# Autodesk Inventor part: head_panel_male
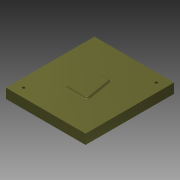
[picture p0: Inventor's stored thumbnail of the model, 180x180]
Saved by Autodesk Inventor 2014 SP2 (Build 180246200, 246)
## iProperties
Created: 2015-02
Part Number: head_panel_male
Material: Generic
Document SubType Name: Modeling
Designer: s41632
Density: 1 g/cm^3
Appearance: Titanium
Author: s41632
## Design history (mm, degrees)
sketch "Sketch9"
  geometry: L1 (0, 0)-(180, 0); L2 (180, 0)-(180, 200); L3 (180, 200)-(0, 200); L4 (0, 200)-(0, 0)
  constraints: 8 end point, 2 parallel, 1 horizontal, 1 perpendicular
  dimensions: "d73" = 200 distance of L3.end L1.start; "d74" = 180 distance between parallel lines of L4 L2
extrude "Extrusion7" new body sketch "Sketch9" distance "d75" = 22; taper "d76" = 0 deg
sketch "Sketch11"
  geometry: L1 (180, 0)-(180, 200) reference; L2 (180, 200)-(0, 200) reference; L3 (0, 200)-(0, 0) reference; L4 (65, 70)-(115, 70); L5 (115, 70)-(105, 130); L6 (105, 130)-(75, 130); L7 (75, 130)-(65, 70); 6 further points
  constraints: 8 end point, 6 midpoint, 2 horizontal alignment, 2 vertical alignment, 1 parallel, 1 perpendicular
  dimensions: "d80" = 30 distance of L5.end L6.end; "d81" = 50 distance of L4.start L4.end; "d82" = 60 distance between parallel lines of L6 L4
extrude "Extrusion8" join sketch "Sketch11" distance "d83" = 3; taper "d84" = 0 deg
fillet "Fillet3" dims "d85" = 5
fillet "Fillet4" dims "d86" = 3
fillet "Fillet5" dims "d87" = 3
sketch "Sketch12"
  geometry: L1 (0, 0)-(180, 0) reference; L2 (180, 0)-(180, 200) reference; L3 (180, 200)-(0, 200) reference; L4 (0, 200)-(0, 0) reference; C1 r 3 at (20, 20); C2 r 3 at (160, 180)
  constraints: 2 centre point, 1 equal radius
  dimensions: "d88" = 6 diameter of C1; "d89" = 20 distance from line of L2 C2.centre; "d90" = 20 distance from line of L3 C2.centre; "d91" = 20 distance from line of L1 C1.centre; "d92" = 20 distance from line of L4 C1.centre
extrude "Extrusion9" cut sketch "Sketch12" distance "d93" = 15; taper "d94" = 0 deg
body "Solid2"
